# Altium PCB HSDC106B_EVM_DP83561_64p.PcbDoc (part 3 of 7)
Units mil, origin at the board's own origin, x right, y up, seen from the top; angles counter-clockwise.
Board outline 8750.24 x 6394.7 mil, 6 copper layers (Top Layer, GND1, SIG1, SIG2, GND2, Bottom Layer), stack 60.4 mil thick; 472 components, 324 nets, 1622 pads, 1086 vias.
Unrouted connection lines stored in the file: 1.
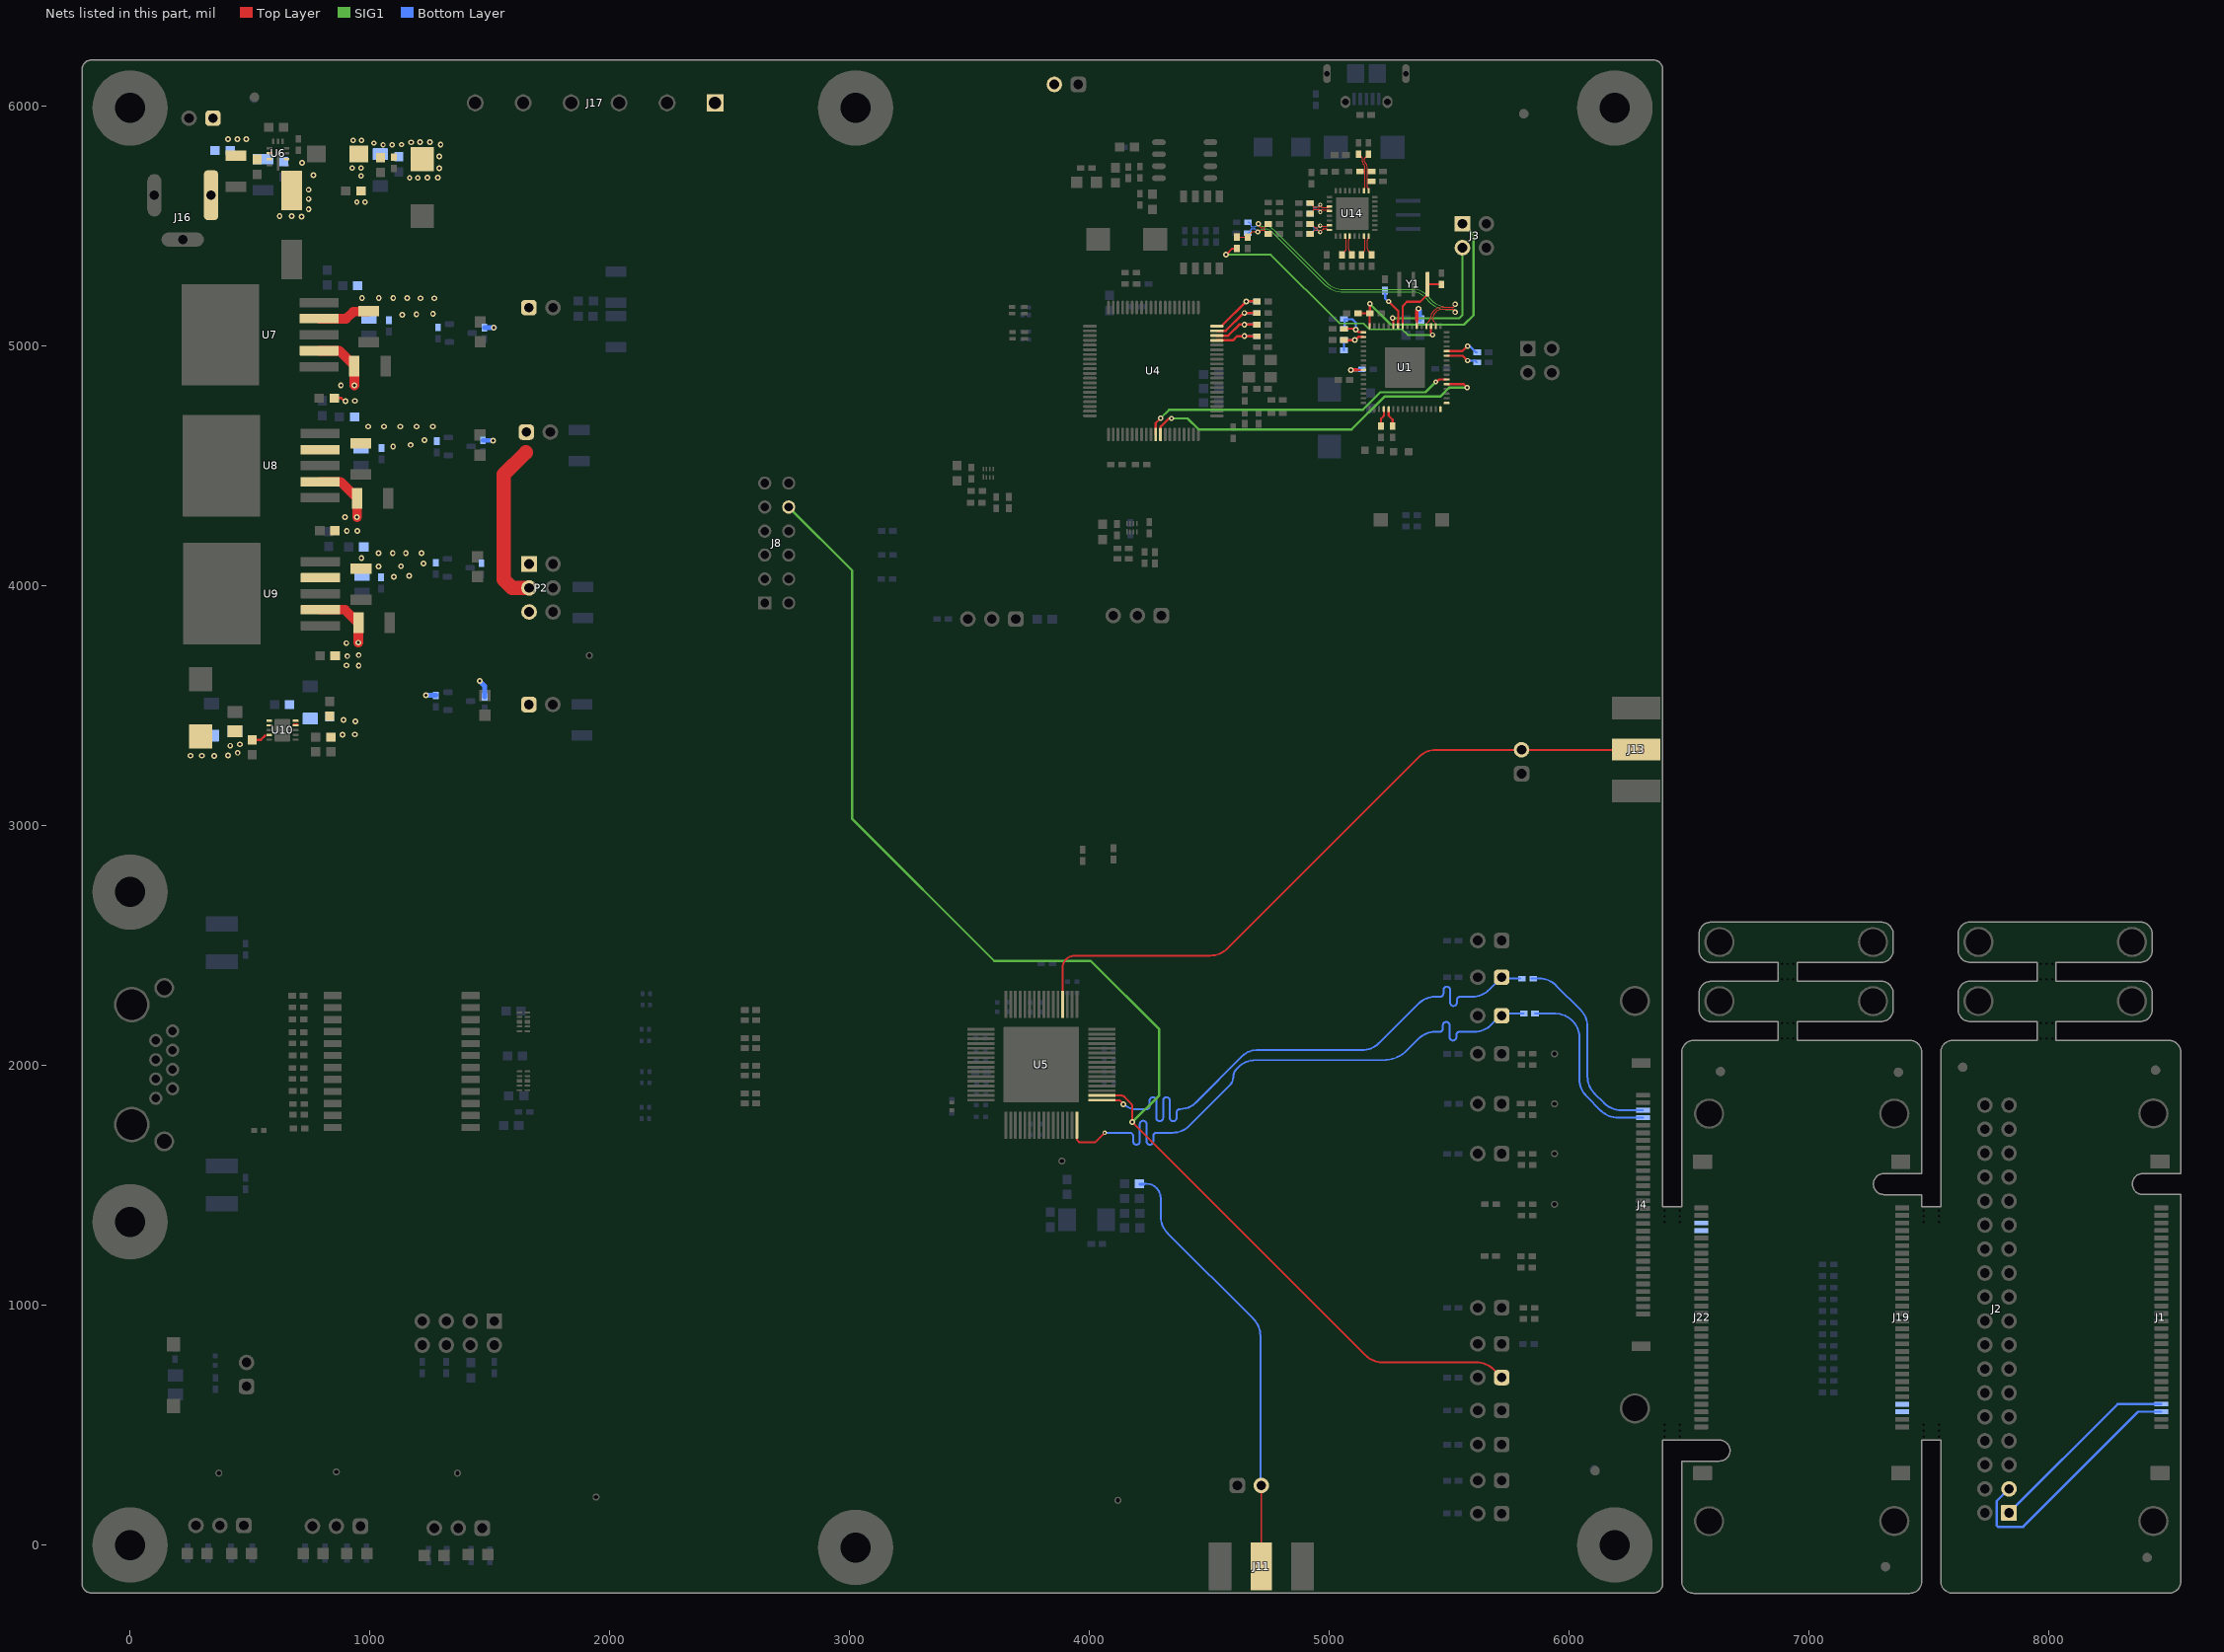
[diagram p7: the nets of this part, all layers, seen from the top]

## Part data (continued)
R74 R200: library part CMP-0026100-2, "RES, 1.00 M, 1%, 0.063 W, AEC-Q200 Grade 0, 0402", Manufacturer=Vishay-Dale, Power_W=63mW, Supplier Part Number 1=541-1.00MLCT-ND, TempCo="100 ppm/C", Tolerance_%=1%, Value2=0.063W, Value_Code=1M00, ValueDisplayed=1.00M
R80: library part CMP-0026993-2, "RES, 100, 5%, 0.1 W, AEC-Q200 Grade 0, 0402", Manufacturer=Panasonic, Power_W=100mW, Supplier Part Number 1=P100JCT-ND, TempCo="200 ppm/C", Tolerance_%=5%, Value2=0.1W, Value_Code=100R, ValueDisplayed=100
R81 R145 R146: "RES, 1.00 M, 1%, 0.063 W, 0402", Manufacturer="Yageo America", PartNumber=RC0402FR-071ML, Power_W=63mW, Supplier Part Number 1=311-1.00MLRCT-ND, TempCo="100 ppm/C", Tolerance_%=1%, Value2=0.063W, Value_Code=1M00, ValueDisplayed=1.00M
R83: library part CMP-0026754-1, "RES, 10.0 k, 1%, 0.063 W, AEC-Q200 Grade 0, 0402", Manufacturer="Stackpole Electronics Inc", Power_W=63mW, Supplier Part Number 1=RMCF0402FT10K0CT-ND, TempCo="100 ppm/C", Tolerance_%=1%, Value2=0.063W, Value_Code=10k0, ValueDisplayed=10.0k
R85 R86 R87 R88 R89: "RES, 2.2 k, 5%, 0.063 W, AEC-Q200 Grade 0, 0402", Manufacturer=Vishay-Dale, PartNumber=CRCW04022K20JNED, Power_W=63mW, Supplier Part Number 1=541-2.2KJCT-ND, TempCo="200 ppm/C", Tolerance_%=5%, Value2=0.063W, Value_Code=2k20, ValueDisplayed=2.2k
R90: "RES, 6.04 k, 1%, 0.1 W, 0603", Manufacturer=Yageo, PartNumber=RC0603FR-076K04L, Power_W=100mW, Supplier Part Number 1=311-6.04KHRCT-ND, TempCo="100 ppm/C", Tolerance_%=1%, Value2=0.1W, Value_Code=6k04, ValueDisplayed=6.04k
R91: "RES, 6.04 k, 1%, 0.1 W, AEC-Q200 Grade 0, 0603", Manufacturer=Vishay-Dale, PartNumber=CRCW06036K04FKEA, Power_W=100mW, Supplier Part Number 1=541-6.04KHCT-ND, TempCo="100 ppm/C", Tolerance_%=1%, Value2=0.1W, Value_Code=6k04, ValueDisplayed=6.04k
R92: library part CMP-0022874-5, "RES, 1.20 k, 1%, 0.1 W, 0603", Manufacturer=Yageo, Power_W=100mW, Supplier Part Number 1=311-1.20KHRCT-ND, TempCo="100 ppm/C", Tolerance_%=1%, Value2=0.1W, Value_Code=1k20, ValueDisplayed=1.20k
R93: library part CMP-0021990-4, "RES, 100 k, 1%, 0.1 W, AEC-Q200 Grade 0, 0603", Manufacturer=Vishay-Dale, Power_W=100mW, Supplier Part Number 1=541-100KHCT-ND, TempCo="100 ppm/C", Tolerance_%=1%, Value2=0.1W, Value_Code=100k
R94 R98 R101: "RES, 2.40 k, 0.1%, 0.1 W, AEC-Q200 Grade 0, 0603", Manufacturer=Panasonic, PartNumber=ERA-3AEB242V, Power_W=100mW, Supplier Part Number 1=P2.4KDBCT-ND, TempCo="25 ppm/C", Tolerance_%=0.1%, Value2=0.1W, Value_Code=2k40, ValueDisplayed=2.40k
R95: library part CMP-0022237-4, "RES, 24.9 k, 1%, 0.1 W, AEC-Q200 Grade 0, 0603", Manufacturer=Vishay-Dale, Power_W=100mW, Supplier Part Number 1=541-24.9KHCT-ND, TempCo="100 ppm/C", Tolerance_%=1%, Value2=0.1W, Value_Code=24k9, ValueDisplayed=24.9k
R96: library part CMP-0022992-5, "RES, 2.55 k, 1%, 0.1 W, 0603", Manufacturer=Yageo, Power_W=100mW, Supplier Part Number 1=311-2.55KHRCT-ND, TempCo="100 ppm/C", Tolerance_%=1%, Value2=0.1W, Value_Code=2k55, ValueDisplayed=2.55k
R100: "RES, 4.22 k, 1%, 0.1 W, AEC-Q200 Grade 0, 0603", Manufacturer=Vishay-Dale, PartNumber=CRCW06034K22FKEA, Power_W=100mW, Supplier Part Number 1=541-4.22KHCT-ND, TempCo="100 ppm/C", Tolerance_%=1%, Value2=0.1W, Value_Code=4k22, ValueDisplayed=4.22k
R102 R103 R104 R105: "RES, 470, 5%, 0.063 W, AEC-Q200 Grade 0, 0402", Manufacturer=Vishay-Dale, PartNumber=CRCW0402470RJNED, Power_W=63mW, Supplier Part Number 1=541-470JCT-ND, TempCo="200 ppm/C", Tolerance_%=5%, Value2=0.063W, Value_Code=470R, ValueDisplayed=470
R106: "RES, 10.0 k, 1%, 0.1 W, 0603", Manufacturer=Yageo, PartNumber=RC0603FR-0710KL, Power_W=100mW, Supplier Part Number 1=311-10.0KHRCT-ND, TempCo="100 ppm/C", Tolerance_%=1%, Value2=0.1W, Value_Code=10k0, ValueDisplayed=10.0k
R107 R114 R117 R123: "RES, 75.0, 1%, 0.063 W, AEC-Q200 Grade 0, 0402", Manufacturer=Vishay-Dale, PartNumber=CRCW040275R0FKED, Power_W=63mW, Supplier Part Number 1=541-75.0LCT-ND, TempCo="100 ppm/C", Tolerance_%=1%, Value2=0.063W, Value_Code=75R0, ValueDisplayed=75.0
R108 R109 R110 R111 R148 R150 R151 R153 R154 R156 R158 R159 R160 R162 R163 R164 R165 R167 R168 R169 R171 R172 R173: library part CMP-0026237-2, "RES, 2.49 k, 1%, 0.063 W, AEC-Q200 Grade 0, 0402", Manufacturer=Vishay-Dale, Power_W=63mW, Supplier Part Number 1=541-2.49KLCT-ND, TempCo="100 ppm/C", Tolerance_%=1%, Value2=0.063W, Value_Code=2k49, ValueDisplayed=2.49k
R152 R155: library part CMP-0026512-2, "RES, 6.04 k, 1%, 0.063 W, AEC-Q200 Grade 0, 0402", Manufacturer=Vishay-Dale, Power_W=63mW, Supplier Part Number 1=541-6.04KLCT-ND, TempCo="100 ppm/C", Tolerance_%=1%, Value2=0.063W, Value_Code=6k04, ValueDisplayed=6.04k
R174: library part CMP-0026768-2, "RES, 100 k, 0.5%, 0.063 W, AEC-Q200 Grade 0, 0402", Manufacturer=Vishay-Dale, Power_W=63mW, Supplier Part Number 1=541-100KAVCT-ND, TempCo="50 ppm/C", Tolerance_%=0.5%, Value2=0.063W, Value_Code=100k
R176: library part CMP-0026036-3, "RES, 165 k, 1%, 0.063 W, AEC-Q200 Grade 0, 0402", Manufacturer=Vishay-Dale, Power_W=63mW, Supplier Part Number 1=541-165KLCT-ND, TempCo="100 ppm/C", Tolerance_%=1%, Value2=0.063W, Value_Code=165k
R177: library part CMP-0026908-3, "RES, 33, 5%, 0.063 W, AEC-Q200 Grade 0, 0402", Manufacturer=Vishay-Dale, Power_W=63mW, Supplier Part Number 1=541-33JCT-ND, TempCo="200 ppm/C", Tolerance_%=5%, Value2=0.063W, Value_Code=33R0, ValueDisplayed=33
R178: library part CMP-0026088-3, "RES, 1.50 k, 1%, 0.063 W, AEC-Q200 Grade 0, 0402", Manufacturer=Vishay-Dale, Power_W=63mW, Supplier Part Number 1=541-1.50KLCT-ND, TempCo="100 ppm/C", Tolerance_%=1%, Value2=0.063W, Value_Code=1k50, ValueDisplayed=1.50k
R180 R183 R196 R199: library part CMP-0026888-3, "RES, 27, 5%, 0.063 W, AEC-Q200 Grade 0, 0402", Manufacturer=Vishay-Dale, Power_W=63mW, Supplier Part Number 1=541-27JCT-ND, TempCo="200 ppm/C", Tolerance_%=5%, Value2=0.063W, Value_Code=27R0, ValueDisplayed=27
R181 R182 R184 R185 R192 R193: library part CMP-0026880-3, "RES, 22, 5%, 0.063 W, AEC-Q200 Grade 0, 0402", Manufacturer=Vishay-Dale, Power_W=63mW, Supplier Part Number 1=541-22JCT-ND, TempCo="200 ppm/C", Tolerance_%=5%, Value2=0.063W, Value_Code=22R0, ValueDisplayed=22
R186 R187 R188 R189 R190 R191 R194 R195: library part CMP-0026027-3, "RES, 15.0 k, 1%, 0.063 W, AEC-Q200 Grade 0, 0402", Manufacturer=Vishay-Dale, Power_W=63mW, Supplier Part Number 1=541-15.0KLCT-ND, TempCo="100 ppm/C", Tolerance_%=1%, Value2=0.063W, Value_Code=15k0, ValueDisplayed=15.0k
S1: library part CMP-0002128-2, "Switch, Slide, SPST 4 poles, SMT", CurrentRating_mA=25A, Manufacturer="CTS Electrocomponents", Supplier Part Number 1=CT2184LPST-ND
S2 S3: library part CMP-0002170-2, "Switch, Normally open, 2.3N force, 200k operations, SMD", CurrentRating_mA=1.001kA, Manufacturer="C&K Components"
SH-J1 SH-J2 SH-J3 SH-J4 SH-J5 SH-J6 SH-J7 SH-J8: library part CMP-0078738-1, "Single Operation 2.54mm Pitch Open Top Jumper Socket", Manufacturer=Harwin, Supplier Part Number 1=952-2881-ND
T1: library part CMP-0090858-1, "350µH LAN 10/100/1000 Base-T Pulse Transformer 1:1 Surface Mount", Digikey Part Number=1000B-5001X-ND, Manufacturer="Pulse Electronics", Operating Temperature Range="-55°C to +125°C", Voltage_Isolation_Vrms=1500Vrms
TP1 VPP_TP1: library part CMP-0003719-1, "Testpoint", Manufacturer="Texas Instruments"
TP2 TP3 TP4 TP5 TP6 TP7 TP8 TP9 TP10: library part CMP-0003719-1, "Testpoint", Manufacturer="Texas Instruments", PartNumber=TP_H0.45P0.75
U1: library part CMP-0039268-4, "16-Bit Ultra-Low-Power Microcontroller, 128KB Flash, 8KB RAM, USB, 12Bit ADC, 2 USCIs, 32Bit HW MPY, RGC0064B (VQFN-64)", Frequency(MHz)=25, Manufacturer="Texas Instruments", Operating Temperature Range="-40 to 85 C", Rating=Catalog, Temp Sensor=Yes
U2 U3: library part CMP-0066434-1, "Dual Bidirectional Multi-Voltage Level Translator, DQE0008A (X2SON-8)", Alternate Manufacturer="Texas Instruments"
U4: library part CMP-0038965-1, "25 MHz Mixed Signal Microcontroller with 128 KB Flash, 8192 B SRAM and 63 GPIOs, -40 to 85 degC, 80-pin QFP (PN), Green (RoHS & no Sb/Br)", Frequency(MHz)=25, Manufacturer="Texas Instruments", Temp Sensor=Yes
U5: library part CMP-0090870-2, "Hi-Reliability, High Immunity, Radiation Resistant, Gigabit Ethernet PHY", Manufacturer="Texas Instruments", Max Supply Voltage=3.45V, Min Supply Voltage=1.045V, Operating Temperature Range="-55°C to +125°C", Part Number=DP83561HBE-EM
U6: library part CMP-0081171-4, "3.8-V to 36-V 2-A Synchronous Step-Down Voltage Regulator, RNX0012B (VQFN-HR-12)", Alternate Manufacturer="Texas Instruments", Alternate PartNumber=LMR33620ARNXR, Operating Temperature Range="-40 to 125 C", Rating=Catalog
U7 U8 U9: library part CMP-0036893-1, "Single Output Fast Transient Response LDO, 1.5 A, Adjustable 1.21 to 20 V Output, 2.1 to 20 V Input, 5-pin DDPAK (KTT), -40 to 125 degC, Green (RoHS & no Sb/Br)", Manufacturer="Texas Instruments"
U10: library part CMP-0036362-5, "Single Output LDO, 500mA, Adj. (0.8 to 3.6V), Programmable Soft-Start, DRC0010J (VSON-10)", Manufacturer="Texas Instruments", Operating Temperature Range="-40 to 125 C", Power Good=TRUE, Rating=Catalog
U11 U12: library part CMP-0073613-3, "4-Channel Ultra-Low-Capacitance IEC ESD Protection Diode, DQA0010A (USON-10)", Alternate Manufacturer="Texas Instruments"
U13: library part CMP-0036447-1, "Single Output Low Noise LDO, 500 mA, Adjustable 1.3 to 6.5 V Output, 2.5 to 16 V Input, 8-pin SOIC (D), -40 to 125 degC, Green (RoHS & no Sb/Br)", Manufacturer="Texas Instruments", Rating=Catalog
U14: library part CMP-0033743-2, "4-Port Full-Speed USB Hub, 3.3V, -40 to 85 degC, 32-Pin QFN (RHB), Green (RoHS & no Sb/Br)", Manufacturer="Texas Instruments", Supply Voltage(s)(V)=3.3
XTAL1: library part CMP-0004620-3, "Crystal, 25 MHz, 18 pF, SMD", Frequency_Fixed=25MHz, Frequency Stability=+/-30ppm, Manufacturer="Abracon Corporation", Supplier Part Number 1=535-10645-1-ND
Y1: library part CMP-0085483-1, "Oscillator, 4 MHz, 700 ppm, 39 pF, SMD", Frequency Tolerance="700 ppm", Frequency_Fixed=4MHz, Load Capacitance="39 pF", Manufacturer=MuRata
Y2: library part CMP-0004637-3, "Crystal, 24 MHz, 20pF, SMD", Frequency Stability=+/-100ppm, Frequency_Fixed=24MHz, Manufacturer="ECS Inc.", Supplier Part Number 1=XC1826CT-ND
Y3: library part CMP-0006147-4, "Resonator, 6 MHz, 15pF SMD", Frequency Stability="+/-0.2 %", Frequency_Fixed=6MHz, Manufacturer=MuRata, Supplier Part Number 1=490-1218-1-ND
ZZ1: library part CMP-0077236-1
ZZ2: library part CMP-0077237-1
ZZ3: library part CMP-0077238-1

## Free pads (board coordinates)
  round 126 hole 106: 2(6273.99,570.39) 2(6273.99,2269.85) 2(6583.67,99.76) 2(6583.67,1799.21) 2(6626.81,2268.37) 2(6626.81,2515.11) 2(7266.97,2268.37) 2(7266.97,2515.11) 2(7355.61,100) 2(7355.61,1799.46) 2(7706.65,2268.68) 2(7706.65,2515.42) 2(8346.81,2268.68) 2(8346.81,2515.42) 2(8436.12,100.39) 2(8436.12,1799.85)
  round 0 hole 10 unplated mask+5: 3(6397.55,452.8) 3(6397.55,477.17) 3(6397.55,501.54) 3(6397.55,1346.69) 3(6397.55,1371.06) 3(6397.55,1395.43) 3(6462.29,452.8) 3(6462.29,477.17) 3(6462.29,501.54) 3(6462.29,1346.69) 3(6462.29,1371.06) 3(6462.29,1395.43) 3(6886.81,2112.61) 3(6886.81,2176.35) 3(6886.81,2359.35) 3(6886.81,2423.09) 3(6911.18,2112.61) 3(6911.18,2176.35) 3(6911.18,2359.35) 3(6911.18,2423.09) 3(6935.55,2112.61) 3(6935.55,2176.35) 3(6935.55,2359.35) 3(6935.55,2423.09) 3(7477.68,453.1) 3(7477.68,477.47) 3(7477.68,501.84) 3(7477.68,1347) 3(7477.68,1371.37) 3(7477.68,1395.74) 3(7542.42,453.1) 3(7542.42,477.47) 3(7542.42,501.84) 3(7542.42,1347) 3(7542.42,1371.37) 3(7542.42,1395.74) 3(7966.65,2112.91) 3(7966.65,2176.65) 3(7966.65,2359.65) 3(7966.65,2423.39) 3(7991.02,2112.91) 3(7991.02,2176.65) 3(7991.02,2359.65) 3(7991.02,2423.39) 3(8015.39,2112.91) 3(8015.39,2176.65) 3(8015.39,2359.65) 3(8015.39,2423.39)

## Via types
v1: diameter 24, hole 12, Top Layer to Bottom Layer, tented both sides, 903 vias
v2: diameter 24, hole 12, Top Layer to Bottom Layer, 65 vias
v3: diameter 18, hole 7.87, Top Layer to Bottom Layer, tented both sides, 53 vias
v4: diameter 22, hole 10, Top Layer to Bottom Layer, tented both sides, 43 vias
v5: diameter 19.68, hole 7.87, Top Layer to Bottom Layer, 21 vias
v6: diameter 22, hole 12, Top Layer to Bottom Layer, tented both sides, 1 vias

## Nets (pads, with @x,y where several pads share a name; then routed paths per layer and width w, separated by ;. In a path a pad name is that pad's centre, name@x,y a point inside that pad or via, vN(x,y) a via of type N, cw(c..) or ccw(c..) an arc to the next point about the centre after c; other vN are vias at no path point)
1V1: C86.2 C87.1 C88.2 J24.1 R28.2 R106.1 R111.1 U10.9 U10.10 | length 67.2
  Top Layer w9: U10.9@690.12,3418.39 685.5,3418.39 681.85,3422.04 697.34,3422.04 U10.9@698,3422.7
  Bottom Layer w20: v1(1233.79,3543.61) 1274.22,3543.61 R111.1@1274.6,3543.23
  other v1: 886,3379.7 937,3380.7 940,3434.7 889.81,3441.28
1V8: C52.1 C53.1 C55.1 J23.1 P2.1 R92.2 R110.1 U7.4 | length 219.4
  Top Layer w40: U7.4@788.42,5114.63 900.93,5114.63 930.31,5144.01 993.35,5144.01 C52.1@995,5145.66
  other v1: 1134.81,5130.28 1193.81,5132.28 1263.31,5134.7 1211,5199.7 1269,5199.7 967,5200.7 1037,5200.7 1097,5200.7 1155,5200.7
2V5: C70.1 C71.1 C73.1 J20.1 P2.3 R96.2 R109.1 U8.4 | length 688.4
  Top Layer w60: 1650,4556.7 1558,4464.7 1558,4026.7 1593,3991.7 P2.3@1663.83,3991.7
  other v1: 1096.81,4581.28 1169.21,4588.37 1227.81,4608.28 993,4664.7 1059,4664.7 1126,4664.7 1194,4664.7 1262,4664.7
3V3: C80.1 C81.1 C83.1 P2.5 R100.2 R102.2 R103.2 R104.2 R105.2 R108.1 U9.4 | length 159.3
  Bottom Layer w20: v1(1458,3603.7) 1478.6,3583.1 R105.2@1478.6,3537.23 ; R103.2@1471.6,4607.23 1511.98,4607.23 v1@1513.6,4605.61 ; R104.2@1477.6,5077.23 v1@1519.22,5077.23
  other v1: 1099.81,4038.28 1163.01,4042.87 1036.21,4081.28 1129.81,4082.28 1223.01,4093.93 964.81,4116.28 1036,4136.7 1095,4136.7 1150,4136.7 1215,4136.7 1513.6,4606.61 1516.6,5077.61
5V: C50.1 C57.1 C58.2 C59.2 C60.2 C61.2 C68.1 C78.1 C85.2 C91.1 C92.2 C93.1 J17.1 J21.2 L1.2 R21.2 R22.2 R24.2 R26.2 R93.2 U7.2 U8.2 U9.2 U10.1 U10.2 U10.4 | length 925.2
  Top Layer w10: R26.2@508.6,3358.6 545.57,3358.6 562.66,3375.68 ; v1(897.6,4771.01) 893.54,4771.01 880.94,4783.61 ; R21.2@851.09,4783.61 880.94,4783.61 ; R21.2@851.09,4783.61 880.94,4783.61 ; R21.2@851.09,4783.61 880.94,4783.61
  Top Layer w40: U7.2@788.42,4980.77 872.93,4980.77 C50.1@933,4920.7 ; U8.2@792.42,4434.77 877.93,4434.77 C68.1@935,4377.7 ; U9.2@793.42,3900.77 896.93,3900.77 944,3853.7 C78.1@948,3853.7 ; v1(935.04,4836.74) C50.1@935.04,4917.7 ; v1(946.04,4286.74) C68.1@946.04,4365.7 ; v1(952.04,3763.74) C78.1@952.04,3846.7
  other v1: 350.6,3290.61 252,3292.1 299.6,3292.1 408.6,3292.61 448.42,3304.28 417.6,3333.61 457.6,3339.61 953,3667.7 902,3668.7 905.6,3707.61 953,3711.7 901.6,3761.61 903.6,4229.61 948,4229.7 896,4286.74 938,4771.7 878.97,4836.74 1239.44,5703.61 1283.6,5703.61 1289.6,5742.61 1289.6,5791.43 1294.64,5840.74 1172.13,5850.04 1209.6,5851.61 1250.6,5851.61
  other v4: 945.6,5600.61 979.6,5600.61 1165.6,5702.61 1200.21,5702.61 963.6,5709.62 925.76,5743.61 963.6,5743.61 1054.89,5839.61 1092.9,5839.61 1131.39,5840.74 1016.33,5847.02 930.06,5858.87 965.6,5858.61
5V-36V: C63.1 C64.1 C65.1 C66.1 C67.1 F1.1 U6.2 U6.9 U6.10
  other v1: 714.83,5540.45 623.6,5542.61 674.6,5542.61 744.6,5571.61 744.6,5613.61 744.6,5652.61 764.6,5712.61 716.75,5764.98 407.79,5863.96 447.23,5863.96 485.27,5863.96
5V-36V_jack: F1.2 J16.1 J18.1
AUTO_RECOVER: J8.10 J39.1 U5.34 | length 5674.6
  Top Layer w8: U5.34@4051.41,1875.27 4130.94,1875.27 cw(c4130.94,1852.95) 4146.73,1868.74 4173.36,1842.1 cw(c4159.75,1828.49) 4179,1828.49 v2(4179,1763.7) 5151.24,791.46 ccw(c5221.96,862.17) 5221.96,762.17 5614.17,762.17 cw(c5614.17,662.17) 5684.88,732.88 J39.1@5718.99,698.77
  SIG1 w10: J8.10@2746,4329 3011,4064 3011,3028 3603,2436 4005.6,2436 4291,2150.6 4291,1875.7 v2(4179,1763.7)
BoardRev0: R49.1 R58.2 U4.77 | length 225.6
  Top Layer w10: U4.77@4531.24,5024.42 4598.31,5024.42 4615.69,5041.8 v1(4646.33,5041.8) R49.1@4697.98,5041.8
  Bottom Layer w10: v1(4646.33,5041.8) R58.2@4697.98,5041.8
BoardRev1: R50.1 R59.2 U4.78 | length 237.4
  Top Layer w10: U4.78@4531.24,5044.1 4578.62,5044.1 4624.59,5090.07 v1(4646.33,5090.07) R50.1@4697.98,5090.07
  Bottom Layer w10: v1(4646.33,5090.07) R59.2@4697.98,5090.07
BoardRev2: R52.1 R60.2 U4.79 | length 249.3
  Top Layer w10: U4.79@4531.24,5063.79 4567.78,5063.79 4639.65,5135.66 4643.65,5135.66 v1(4646.33,5138.34) R52.1@4697.98,5138.34
  Bottom Layer w10: v1(4646.33,5138.34) R60.2@4697.98,5138.34
BoardRev3: R53.1 R61.2 U4.80 | length 255.5
  Top Layer w10: U4.80@4531.24,5083.47 4553.38,5083.47 4554.22,5084.31 4554.22,5087.23 v1(4653.6,5186.61) R53.1@4697.98,5186.61
  Bottom Layer w10: v1(4653.6,5186.61) R61.2@4697.98,5186.61
CLKOUT: J13.1 J14.2 U5.52 | length 2920.1
  Top Layer w8: U5.52@3888.14,2255.08 3888.14,2407.15 cw(c3939.6,2407.15) 3939.6,2458.61 4504.18,2458.61 ccw(c4504.18,2558.61) 4574.89,2487.9 5374.44,3287.45 cw(c5445.15,3216.74) 5445.15,3316.74 J14.2@5801.67,3316.74 6276.29,3316.74 ccw(c6276.29,3321.41) J13.1@6279.6,3318.11
COL: J6.1 R32.1 U5.32 | length 2515.6
  Top Layer w8: U5.32@3947.2,1751.38 3947.2,1690.5 3957,1680.7 4025,1680.7 v3(4064,1719.7)
  Bottom Layer w8: v3(4064,1719.7) 4136,1719.7 4168,1719.7 cw(c4168,1705.7) 4182,1705.7 4182,1683.7 ccw(c4196,1683.7) 4210,1683.7 4210,1755.7 cw(c4224,1755.7) 4238,1755.7 4238,1683.7 ccw(c4252,1683.7) 4266,1683.7 4266,1705.7 cw(c4280,1705.7) 4280,1719.7 4318,1719.7 4346.26,1719.7 ccw(c4346.26,1819.7) 4416.97,1748.99 4585.46,1917.48 ccw(c4551.34,1951.61) 4599.6,1951.61 cw(c4647.88,1951.61) 4613.74,1985.75 4621.21,1993.22 cw(c4691.92,1922.5) 4691.92,2022.5 5226.87,2022.5 5226.93,2022.5 ccw(c5226.93,2157.06) 5322.17,2062.01 5371.55,2111.39 cw(c5442.26,2040.68) 5442.26,2140.68 5455.5,2140.68 5459.5,2140.68 ccw(c5459.5,2154.68) 5473.5,2154.68 5473.5,2167.57 cw(c5487.5,2167.57) 5501.5,2167.57 5501.5,2118.5 ccw(c5515.5,2118.5) 5529.5,2118.5 5529.5,2126.68 cw(c5543.5,2126.68) 5543.5,2140.68 5574.38,2140.68 5604.87,2140.68 ccw(c5604.87,2240.68) 5675.58,2169.97 5715.91,2210.3 cw(c5730.84,2195.37) 5730.84,2216.48 R32.1@5810.6,2216.48
COL_1: J1.54 J2.1 | length 823.2
  Bottom Layer w10: J2.1@7833.6,134.61 8286.79,587.8 J1.54@8469.11,587.8
COL_2: J22.54
COL_CS: J4.54 R32.2 | length 763.6
  Bottom Layer w8: R32.2@5857.84,2216.48 5942.6,2216.48 cw(c5942.6,2116.48) 6042.6,2116.48 6042.6,1943.35 ccw(c6142.6,1943.35) 6071.89,1872.63 6133.03,1811.49 ccw(c6203.74,1882.2) 6203.74,1782.2 J4.54@6308.86,1782.2
COL_LP: J19.54
CRS: J41.1 R33.1 U5.33 | length 2431.2
  Top Layer w8: U5.33@4051.41,1855.59 4125.41,1855.59 v1(4142,1839)
  Bottom Layer w8: v1(4142,1839) 4142,1839.7 ccw(c4194.78,1892.48) 4194.78,1817.84 4233.14,1817.84 4237.14,1817.84 ccw(c4237.14,1831.84) 4251.14,1831.84 4251.14,1853.84 cw(c4265.14,1853.84) 4279.14,1853.84 4279.14,1781.84 ccw(c4293.14,1781.84) 4307.14,1781.84 4307.14,1853.84 cw(c4321.14,1853.84) 4335.14,1853.84 4335.14,1781.84 ccw(c4349.14,1781.84) 4363.14,1781.84 4363.14,1803.84 cw(c4377.14,1803.84) 4377.14,1817.84 4377.62,1817.84 4412,1824.57 ccw(c4377.62,1908.92) 4416,1826.32 ccw(c4377.62,1908.92) 4442,1844.49 ; 4442.03,1844.52 4636.85,2039.33 cw(c4696.66,1979.52) 4696.66,2064.11 5136.5,2064.11 ccw(c5136.5,2164.11) 5207.21,2093.4 5371.58,2257.76 cw(c5442.29,2187.05) 5442.29,2287.05 5458,2287.05 5462,2287.05 ccw(c5462,2301.05) 5476,2301.05 5476,2315.17 cw(c5490,2315.17) 5504,2315.17 5504,2262.55 ccw(c5518,2262.55) 5532,2262.55 5532,2273.05 cw(c5546,2273.05) 5546,2287.05 5565,2287.05 5596.35,2287.05 ccw(c5596.35,2387.05) 5667.06,2316.34 J41.1@5718.99,2368.28 ccw(c5730.68,2379.96) 5730.68,2363.43 R33.1@5795.53,2363.43
CRS_1: J1.56 J2.3 | length 1060.9
  Bottom Layer w10: J2.3@7833.6,234.61 7782.6,183.61 7782.6,82.46 7788.46,76.61 7893.15,76.61 8372.85,556.3 J1.56@8469.11,556.3
CRS_2: J22.56
CRS_CS: J4.56 R33.2 | length 846.8
  Bottom Layer w8: R33.2@5842.77,2363.43 5874.86,2363.43 cw(c5874.86,2263.43) 5945.57,2334.14 6047.31,2232.41 cw(c5976.6,2161.7) 6076.6,2161.7 6076.6,1954.03 ccw(c6176.6,1954.03) 6105.89,1883.32 6146.21,1842.99 ccw(c6216.93,1913.7) 6216.93,1813.7 J4.56@6308.86,1813.7
CRS_LP: J19.56
D0_N: C118.1 R181.2 U14.2 | length 208.7
  Top Layer w5: R181.2@5122,5801.38 ccw(c5131.51,5801.38) 5124.78,5794.66 5130.05,5789.39 ccw(c5133.09,5792.43) 5133.09,5788.13 cw(c5133.09,5783.83) 5136.13,5786.87 cw(c5132.1,5782.84) 5137.8,5782.84 5137.8,5771.38 5137.87,5771.32 5137.87,5769.67 ccw(c5153.65,5769.67) 5142.49,5758.51 5144,5757 cw(c5130.33,5743.33) 5149.66,5743.33 5149.66,5720 ; C118.1@5127.62,5729 C118.1@5139.61,5729 ; U14.2@5144.62,5647.99 5144.62,5651.32 cw(c5153.23,5651.32) 5147.14,5657.4 ccw(c5141.06,5663.49) 5149.66,5663.49 5149.66,5720 ; 5149.66,5739.06 cw(c5139.61,5739.06) C118.1@5139.61,5729 ; C118.1@5139.61,5729 5140.66,5729 cw(c5140.66,5720) 5149.66,5720
D0_P: C119.1 R178.1 R182.2 U14.1 | length 165.4
  Top Layer w5: R182.2@5163.41,5800.88 cw(c5153.9,5800.88) 5160.62,5794.16 5155.43,5788.97 cw(c5152.21,5792.18) 5152.21,5787.63 ccw(c5152.21,5783.09) 5149,5786.3 ccw(c5152.85,5782.45) 5147.47,5783.28 ccw(c5152.85,5782.45) 5147.4,5782.45 5147.4,5775.36 5147.47,5775.29 5147.47,5769.72 ccw(c5153.75,5769.72) 5149.31,5765.27 5150.83,5763.75 cw(c5130.46,5743.38) 5159.26,5743.38 5159.26,5663.49 ccw(c5167.87,5663.49) 5161.78,5657.4 cw(c5155.7,5651.32) 5164.31,5651.32 U14.1@5164.31,5647.99
D1_N: C121.1 R184.2 U14.11 | length 160.3
  Top Layer w5: R184.2@4919.6,5596.61 cw(c4919.6,5588.77) 4925.14,5594.31 4930.46,5589 cw(c4926.33,5584.88) 4932.16,5584.88 4932.16,5584.54 ccw(c4937.16,5584.54) 4933.62,5581 ccw(c4937.16,5584.54) 4937.16,5579.53 4952.53,5579.54 ccw(c4952.53,5589.61) v3(4962.6,5589.61) ccw(c4974.22,5589.61) 4974.22,5577.99 4975,5577.99 4988.13,5577.99 ccw(c4988.13,5582.99) 4989,5578.07 cw(c4991.08,5566.3) 4991.08,5578.25 4995.92,5578.25 ccw(c4995.92,5583.25) U14.11@5000.92,5583.03
  Bottom Layer w5: C121.1@4919.6,5596.61 cw(c4919.6,5588.77) 4925.14,5594.31 4930.45,5589 cw(c4926.33,5584.88) 4932.16,5584.88 4932.16,5584.54 ccw(c4937.16,5584.54) 4933.62,5581 ccw(c4937.16,5584.54) 4937.16,5579.53 4942.21,5579.54 ccw(c4942.21,5596.73) 4954.36,5584.56 4957.15,5587.35 cw(c4962.6,5581.9) v3(4962.6,5589.61)
D1_P: C120.1 R185.2 U14.12 | length 158.2
  Top Layer w5: R185.2@4920.22,5552.61 ccw(c4920.22,5559.83) 4925.33,5554.72 4930.72,5560.12 ccw(c4926.38,5564.46) 4932.52,5564.46 4932.52,5564.94 cw(c4937.52,5564.94) 4933.99,5568.47 cw(c4937.52,5564.94) 4937.52,5569.94 4952.27,5569.94 cw(c4952.27,5559.61) v3(4962.6,5559.61) cw(c4971.38,5559.61) 4971.38,5568.39 4988.13,5568.39 cw(c4988.13,5563.39) 4988.97,5568.32 ccw(c4991.08,5580.08) 4991.08,5568.13 4995.92,5568.13 cw(c4995.92,5563.13) U14.12@5000.92,5563.37
  Bottom Layer w5: C120.1@4920.22,5552.61 ccw(c4920.22,5559.83) 4925.33,5554.72 4930.72,5560.12 ccw(c4926.38,5564.46) 4932.52,5564.46 4932.52,5564.94 cw(c4937.52,5564.94) 4933.99,5568.47 cw(c4937.52,5564.94) 4937.52,5569.94 4942.29,5569.94 cw(c4942.29,5552.3) 4954.76,5564.77 4958.03,5561.5 ccw(c4962.6,5566.07) v3(4962.6,5559.61)
D2_N: C125.1 R192.2 U14.15 | length 134.9
  Top Layer w5: R192.2@4920.03,5509.5 cw(c4920.03,5500) 4926.75,5506.72 4933.72,5499.75 ccw(c4947.36,5513.39) 4947.36,5494.1 ccw(c4947.36,5505.72) 4955.57,5497.5 4960.02,5501.95 cw(c4961.6,5500.37) v3(4961.6,5502.61) ; v3@4962.26,5502.61 ccw(c4970.37,5510.71) 4968.81,5499.36 ccw(c4970.37,5510.71) 4970.37,5499.25 4985.42,5499.25 ccw(c4985.42,5507.86) 4991.51,5501.77 cw(c4997.6,5495.68) 4997.6,5504.29 U14.15@5000.92,5504.29
  Bottom Layer w5: C125.1@4920.03,5509.5 cw(c4920.03,5500) 4926.75,5506.72 4932.06,5501.41 cw(c4929.1,5498.46) 4933.28,5498.46 ccw(c4937.46,5498.46) 4934.5,5495.51 ccw(c4938.62,5499.63) 4938.62,5493.8 4941.64,5493.8 4946.91,5493.8 ccw(c4946.91,5506.51) 4951.02,5494.49 ccw(c4946.91,5506.51) v3@4955.89,5497.53
D2_P: C124.1 R193.2 U14.16 | length 142.1
  Top Layer w5: R193.2@4920.03,5468.5 ccw(c4920.03,5478.01) 4926.75,5471.29 4934.74,5479.28 cw(c4947.36,5466.66) 4944.11,5484.2 cw(c4947.36,5466.66) 4947.36,5484.5 cw(c4947.36,5472.64) 4955.75,5481.03 4959.91,5476.87 ccw(c4962,5478.95) v3(4962,5476) 4972.7,5486.7 cw(c4975.99,5482.93) 4973.04,5486.97 ccw(c4961.6,5502.61) 4974.7,5488.33 cw(c4978.08,5484.65) 4978.11,5489.65 4985.42,5489.65 cw(c4985.42,5481.04) 4991.51,5487.13 ccw(c4997.6,5493.21) 4997.6,5484.61 U14.16@5000.92,5484.61
  Bottom Layer w5: C124.1@4920.03,5468.5 ccw(c4920.03,5478.01) 4926.75,5471.29 4932.06,5476.59 ccw(c4929.1,5479.55) 4933.28,5479.55 cw(c4937.46,5479.55) 4934.5,5482.5 cw(c4938.62,5478.38) 4938.62,5484.2 4945.62,5484.2 4949.1,5484.2 cw(c4949.1,5475.82) 4949.2,5484.2 cw(c4949.1,5475.82) 4950.44,5484.1 cw(c4949.1,5475.82) 4955.03,5481.75 ; v3@4960.02,5474.52 v3@4963,5474.52
DM3: R188.2 U14.19 | length 86.2
  Top Layer w5: R188.2@5053.44,5380.94 5053.44,5384.88 5067.97,5399.41 ; U14.19@5065.88,5459.02 5065.88,5455.69 ccw(c5074.49,5455.69) 5068.4,5449.61 cw(c5062.32,5443.52) 5070.92,5443.52 5070.92,5406.53 cw(c5060.85,5406.53) 5067.98,5399.42
DM4: R190.2 U14.23 | length 84.3
  Top Layer w5: R190.2@5134.6,5381.23 cw(c5144.1,5381.23) 5137.38,5387.95 R190.2@5143.91,5394.48 ; R190.2@5143.94,5394.48 5144.98,5395.52 ccw(c5133.68,5406.82) 5149.66,5406.82 5149.66,5443.52 ccw(c5141.06,5443.52) 5147.14,5449.61 cw(c5153.23,5455.69) 5144.62,5455.69 U14.23@5144.62,5459.02
DP3: R189.2 U14.20 | length 76.5
  Top Layer w5: U14.20@5085.57,5459.02 5085.57,5455.69 cw(c5076.96,5455.69) 5083.04,5449.61 ccw(c5089.13,5443.52) 5080.52,5443.52 5080.52,5406.53 ccw(c5106.92,5406.53) R189.2@5088.24,5387.88 ; R189.2@5088.25,5387.86 R189.2@5089.63,5386.48
DP4: R191.2 U14.24 | length 86.5
  Top Layer w5: U14.24@5164.31,5459.02 5164.31,5455.69 cw(c5155.7,5455.69) 5161.78,5449.61 ccw(c5167.87,5443.52) 5159.26,5443.52 5159.26,5406.82 ccw(c5175.24,5406.82) 5163.94,5395.52 5164.11,5395.36 ccw(c5166.23,5397.48) 5166.23,5394.48 cw(c5166.23,5391.47) 5168.35,5393.6 5174,5387.95 cw(c5167.28,5381.23) R191.2@5176.79,5381.23
EXT_REF_CLK: J11.1 J12.2 R84.1 | length 1840.8
  Top Layer w8: J11.1@4716.6,-89.39 J12.2@4716.6,248.61
  Bottom Layer w8: R84.1@4209.09,1506.61 4228.06,1506.61 4237.58,1506.61 cw(c4237.58,1447.28) 4296.91,1447.28 4296.91,1371.36 ccw(c4396.91,1371.36) 4326.19,1300.65 4683.31,943.53 cw(c4612.6,872.82) 4712.6,872.82 J12.2@4712.6,248.61 ; R84.1@4209.22,1503.23 R84.1@4228.06,1503.23
EZFET_AVBUS: C2.1 R3.1 R5.2 U1.1 | length 206.9
  Top Layer w9: R3.1@5066.24,5073.7 5107,5073.7 5110,5070.7 v1(5110,5068.7) 5110,5066.7 5114,5066.7 5122.37,5058.33 U1.1@5142.77,5058.33
  Bottom Layer w9: R5.2@5064.24,5072.61 5064.24,5112.7 5096.05,5112.7 5110,5098.75 v1(5110,5068.7)
EZFET_AVCOUT2ADC: C3.1 R4.1 R6.2 U1.2 | length 175.4
  Top Layer w10: C3.1@5061.22,5025.7 5061.27,5025.65 5106.55,5025.65 v1(5106.6,5025.61) 5108.5,5025.61 5121.54,5038.65 U1.2@5142.77,5038.65
  Bottom Layer w10: R6.2@5061.22,4982.7 R4.1@5061.22,5025.7 5061.27,5025.65 5106.55,5025.65 v1(5106.6,5025.61)
EZFET_LED0: R1.2 U1.20 | length 75.5
  Top Layer w9: R1.2@5216,4668.67 5216,4697.67 5227.39,4709.06 U1.20@5227.39,4739.43
EZFET_LED1: R2.2 U1.21 | length 77.8
  Top Layer w9: U1.21@5247.1,4737.47 5247.08,4710.62 5264,4693.7 R2.2@5264,4666.7
EZFET_PUD_N: C128.1 R196.1 U1.52 | length 1245
  Top Layer w5: v4@4704.61,5509.56 ccw(c4720.37,5509.56) 4720.35,5493.8 4726.79,5493.8 ccw(c4726.79,5499.63) 4730.91,5495.51 ccw(c4727.95,5498.46) 4732.13,5498.46 cw(c4736.31,5498.46) 4733.35,5501.42 4738.66,5506.72 cw(c4745.38,5500) R196.1@4745.38,5509.5 ; U1.52@5404.58,5083.92 cw(c5429.34,5083.92) 5411.83,5101.43 5415.67,5105.27 ; 5415.68,5105.28 ccw(c5404.95,5115.98) 5416.46,5106.12 ccw(c5404.95,5115.98) 5420.11,5115.98 cw(c5473.7,5109.29) 5473.7,5163.3 5513.3,5163.3 ccw(c5513.3,5175) v1(5525,5175)
  SIG1 w5: v4(4703.6,5510.61) 4703.6,5510.11 ccw(c4730.03,5536.54) 4730.03,5499.16 4732.55,5499.16 cw(c4732.55,5446.07) 4770.09,5483.61 4987.41,5266.29 ccw(c5058.12,5337) 5058.12,5237 5348.03,5237 cw(c5348.03,5155.73) 5405.5,5213.2 5426.41,5192.29 ccw(c5497.12,5263) 5496.98,5163 ccw(c5497.12,5263) 5497.12,5163 5513,5163 ccw(c5513,5175) v1(5525,5175)
  Bottom Layer w5: C128.1@4665.22,5515.06 ccw(c4661.24,5511.07) C128.1@4661.24,5516.7 cw(c4661.24,5505.06) 4672.89,5505.06 4672.89,5503.71 ccw(c4677.89,5503.71) 4674.35,5500.18 ccw(c4677.89,5503.71) 4677.89,5498.71 4685.62,5498.71 ccw(c4685.62,5519.15) 4700.06,5504.69 v4@4701.92,5506.55
EZFET_PUD_P: C127.1 R197.1 R199.1 R200.2 U1.50 | length 1317.4
  Top Layer w5: R197.1@4614.59,5454.39 R200.2@4659.87,5454.39 4659.87,5458.33 4673.27,5471.73 ; 4673.28,5471.75 cw(c4685.03,5459.97) 4685.03,5476.61 v4(4702.6,5476.61) ; v4@4703.6,5484.2 4721,5484.2 4726.79,5484.2 cw(c4726.79,5478.38) 4730.91,5482.5 cw(c4727.95,5479.55) 4732.13,5479.55 ccw(c4736.31,5479.55) 4733.35,5476.6 4738.66,5471.29 ccw(c4745.38,5478.01) R199.1@4745.38,5468.5 ; U1.50@5443.95,5083.92 ccw(c5414.66,5083.92) 5435.37,5104.63 cw(c5447.12,5116.38) 5430.5,5116.38 5430.5,5116.61 cw(c5473.7,5110) 5473.7,5153.7 5513.3,5153.7 cw(c5513.3,5142) v1(5525,5142)
  SIG1 w5: v4(4702.6,5476.61) 4703.1,5476.61 cw(c4730.74,5448.96) 4730.74,5488.06 4732.5,5488.06 cw(c4732.5,5445.94) 4762.28,5475.72 4979.59,5258.41 ccw(c5058.08,5336.9) 5058.08,5225.9 5348,5225.9 cw(c5348,5155.65) 5397.68,5205.32 5421.12,5181.88 ccw(c5493.5,5254.26) 5493.5,5151.9 5515.1,5151.9 cw(c5515.1,5142) v1(5525,5142)
  Bottom Layer w5: C127.1@4659.87,5471.7 ccw(c4659.87,5478.71) 4664.82,5473.75 4670.25,5479.18 ccw(c4665.84,5483.6) 4672.08,5483.6 4672.08,5484.11 cw(c4677.08,5484.11) 4673.55,5487.65 cw(c4677.08,5484.11) 4677.08,5489.11 4685.35,5489.11 cw(c4685.35,5477.67) 4689.09,5488.49 cw(c4685.35,5477.67) 4693.43,5485.77 v4(4702.6,5476.61)
EZFET_PUR: R197.2 U1.51 | length 1096.6
  Top Layer w8: v1(4569.63,5381.56) 4595.22,5407.15 R197.2@4614.59,5407.15 ; U1.51@5424.26,5085.01 5424.26,5053.5 v4(5430.97,5046.79)
  SIG1 w8: v1(4569.63,5381.56) 4756.44,5381.56 5043.21,5094.79 5142.01,5094.79 5166.64,5070.17 5303.83,5070.17 5327.21,5046.79 v4(5430.97,5046.79)
EZFET_RST: C8.1 J3.1 R8.1 U1.64 | length 1028.5
  Top Layer w9: R8.1@5119.62,5136.7 C8.1@5169.38,5136.7 5168.32,5135.64 U1.64@5168.32,5083.92
  Top Layer w10: C8.1@5169.38,5136.7 v4(5169.38,5176.7)
  SIG1 w10: v4(5169.38,5176.7) 5256.38,5089.7 5561.69,5089.7 5602,5130.01 5602,5463.7 J3.1@5555,5510.7
EZFET_SBW_RST: R10.1 U1.43 | length 136.4
  Top Layer w9: U1.43@5489.22,4959.91 5555.79,4959.91 v4(5576,4939.7)
  Bottom Layer w9: v4(5576,4939.7) 5607.38,4939.7 R10.1@5614.38,4932.7
EZFET_SBW_TST: R9.1 U1.44 | length 144.6
  Top Layer w9: U1.44@5489.22,4979.59 5555.02,4979.59 v4(5576,5000.57)
  Bottom Layer w9: v4(5576,5000.57) 5586.13,5000.57 5612,4974.7 R9.1@5614.38,4974.7
EZFET_TEST: J3.3 U1.59 | length 609.4
  Top Layer w9: v4(5264.6,5117.61) 5266.56,5115.65 5266.56,5084.15 U1.59@5266.78,5083.92 U1.59@5266.77,5079.86
  SIG1 w9: v4@5266.6,5116.61 5541.8,5116.61 5555,5129.81 J3.3@5555,5406.64
EZFET_UARTCTS: U1.32
EZFET_UARTRTS: U1.33
EZFET_UARTRXD: U1.38 U4.51 | length 1335.9
  Top Layer w9: v4(5443.94,4851.02) 5447.46,4851.02 5458.05,4861.61 5489.1,4861.61 U1.38@5489.22,4861.48
  Top Layer w10: U4.51@4276.31,4631.7 4276.31,4679.02 v4(4297,4699.7)
  SIG1 w10: v4(4297,4699.7) 4332,4734.7 5139.69,4734.7 5212.69,4807.7 5400.63,4807.7 v4(5443.94,4851.02)
EZFET_UARTTXD: U1.37 U4.52 | length 1505.2
  Top Layer w9: U1.37@5489.22,4841.8 5559.9,4841.8 v4(5574,4827.7)
  Top Layer w10: U4.52@4296,4631.7 4296.91,4632.61 4296.91,4664.15 4331.45,4698.7 v4@4340.76,4698.7
  SIG1 w10: v4(4342,4698.7) 4409.39,4698.7 4455.48,4652.61 5092.73,4652.61 5229.95,4789.83 5462.63,4789.83 5500.5,4827.7 v4(5574,4827.7)
EZFET_VREF: C1.1 U1.9 | length 100.2
  Top Layer w9: 5116.15,4900.85 U1.9@5142.77,4900.85
  Top Layer w15: v1(5089.85,4900.85) 5116.15,4900.85
  Bottom Layer w15: v1(5089.85,4900.85) 5133.22,4900.85 C1.1@5135.98,4903.61
EZFET_VUSB: C9.1 U1.54 | length 126.8
  Top Layer w9: U1.54@5365.21,5083.92 5365.21,5109.48
  Top Layer w15: 5365.21,5109.48 5365.21,5150.21 v1(5371.6,5156.61)
  Bottom Layer w15: v1(5371.6,5156.61) 5378.99,5149.22 C9.1@5378.99,5108.2
EZFET_XIN: C5.1 U1.57 Y1.3 | length 308.3
  Top Layer w9: U1.57@5306.15,5083.92 5306.15,5167.33 5323.94,5185.11 5378.64,5185.11 5405.46,5211.93 5406.28,5211.93 5409.65,5215.3 Y1.3@5409.65,5258.61 5466.98,5258.61 C5.1@5467.6,5257.98
EZFET_XOUT: R7.1 U1.58 | length 165.7
  Top Layer w9: v4(5247,5186.52) 5287.97,5145.55 5287.97,5107.92 5286.46,5106.41 U1.58@5286.47,5083.92
  Bottom Layer w9: R7.1@5233,5224.9 5233,5198.29 5244.77,5186.52 v4(5247,5186.52)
